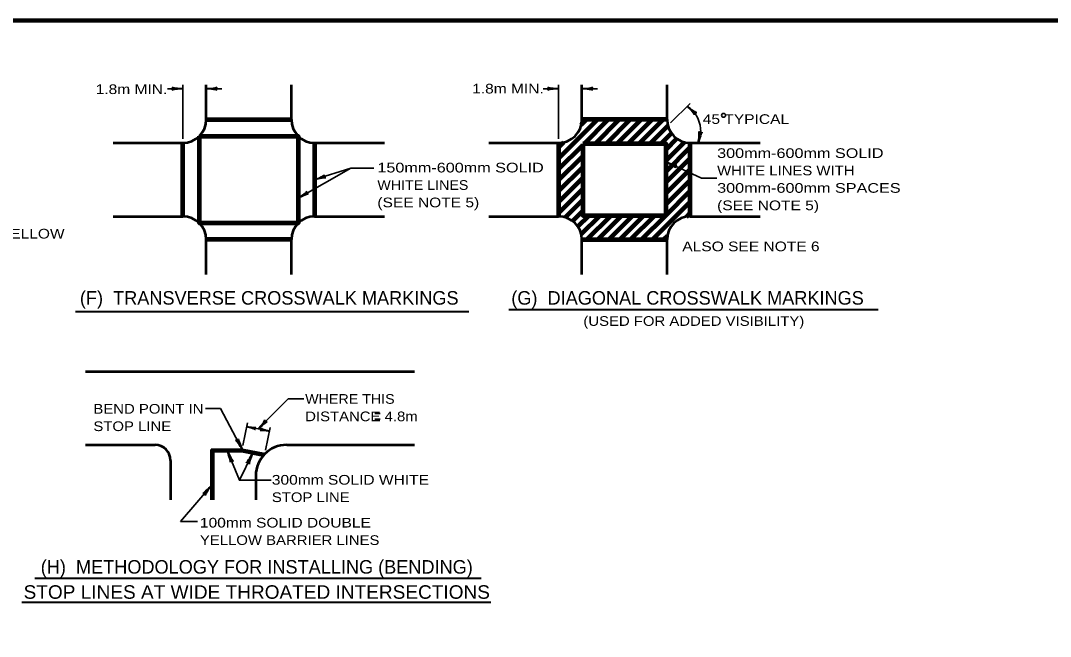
# Model space of a CAD drawing. Extents: x -90 to 765, y -1136 to -592.
# Drawn here: x 218.6 to 537.7, y -789.1 to -598.1 of the extents above; entities that cross this region are included whole.
import ezdxf
from ezdxf.enums import TextEntityAlignment as Align

# ---------------------------------------------------------------- set-up
doc = ezdxf.new("R2010")
doc.units = 0
doc.header["$LTSCALE"] = 1.2
doc.layers.add('1', color=7, linetype='Continuous', lineweight=90)

msp = doc.modelspace()

# ---------------------------------------------------------------- linework, layer by layer
at = {"layer": '1', "lineweight": 35}
for p, q in [((268.927, -634.812), (268.927, -618.013)), ((385.327, -634.812), (385.327, -618.013)), ((264.127, -619.212), (268.927, -619.212)), ((276.127, -619.212), (280.927, -619.212)), ((380.527, -619.212), (385.327, -619.212)), ((392.527, -619.212), (397.327, -619.212)), ((420.026, -629.849), (426.071, -623.803)), ((320.997, -643.903), (304.636, -653.164)), ((320.997, -643.903), (309.727, -647.413)), ((320.997, -643.903), (328.091, -643.903)), ((418.636, -641.864), (429.576, -646.983)), ((429.576, -646.983), (434.376, -646.983)), ((292.204, -724.718), (301.545, -715.368)), ((301.545, -715.368), (306.345, -715.368)), ((275.891, -718.43), (280.527, -718.43)), ((287.283, -731.075), (280.527, -718.43)), ((288.935, -722.839), (287.519, -729.898)), ((288.699, -724.015), (295.71, -725.421)), ((295.946, -724.245), (294.531, -731.304)), ((277.683, -742.387), (268.121, -753.418)), ((286.43, -740.631), (296.226, -740.631)), ((268.121, -753.418), (273.42, -753.418))]:
    msp.add_line(p, q, dxfattribs=at)
at = {"layer": '1', "lineweight": 53}
for p, q in [((276.127, -628.812), (276.127, -618.013)), ((302.527, -628.812), (302.527, -618.013)), ((392.527, -628.812), (392.527, -618.013)), ((418.927, -628.812), (418.927, -618.013)), ((247.327, -636.013), (268.927, -636.013)), ((309.727, -636.013), (331.327, -636.013)), ((363.727, -636.013), (385.327, -636.013)), ((426.127, -636.013), (447.727, -636.013)), ((247.327, -658.812), (268.927, -658.812)), ((309.727, -658.812), (331.327, -658.812)), ((363.727, -658.812), (385.327, -658.812)), ((426.127, -658.812), (447.727, -658.812)), ((276.127, -676.812), (276.127, -666.013)), ((302.527, -676.812), (302.527, -666.013)), ((392.527, -676.812), (392.527, -666.013)), ((418.927, -676.812), (418.927, -666.013)), ((238.683, -706.869), (340.683, -706.869)), ((238.683, -729.669), (260.283, -729.669)), ((301.083, -729.669), (340.683, -729.669)), ((277.683, -731.075), (277.683, -746.701)), ((277.683, -731.075), (287.283, -731.075)), ((278.283, -731.675), (278.283, -746.701)), ((278.283, -731.675), (287.224, -731.675)), ((287.224, -731.675), (293.816, -732.996)), ((287.283, -731.075), (294.295, -732.481)), ((265.083, -734.469), (265.083, -746.701)), ((291.483, -739.269), (291.483, -746.701))]:
    msp.add_line(p, q, dxfattribs=at)
at = {"layer": '1'}
for p, q in [((276.127, -628.812), (302.527, -628.812)), ((385.327, -640.816), (397.331, -628.812)), ((392.32, -630.43), (393.937, -628.812)), ((418.927, -628.812), (392.527, -628.812)), ((393.234, -636.304), (400.725, -628.812)), ((396.628, -636.304), (404.119, -628.812)), ((400.022, -636.304), (407.513, -628.812)), ((403.416, -636.304), (410.907, -628.812)), ((406.81, -636.304), (414.301, -628.812)), ((410.204, -636.304), (417.696, -628.812)), ((413.598, -636.304), (419.186, -630.717)), ((416.993, -636.304), (420.292, -633.004)), ((418.636, -638.055), (422, -634.69)), ((268.927, -658.812), (268.927, -636.013)), ((309.727, -636.013), (309.727, -658.812)), ((385.327, -637.422), (386.937, -635.813)), ((385.327, -636.013), (385.327, -658.812)), ((385.327, -644.21), (392.818, -636.719)), ((418.636, -641.449), (424.326, -635.759)), ((418.636, -644.843), (426.127, -637.351)), ((426.127, -658.812), (426.127, -636.013)), ((385.327, -647.605), (392.818, -640.113)), ((418.636, -648.237), (426.127, -640.746)), ((385.327, -650.999), (392.818, -643.507)), ((418.636, -651.631), (426.127, -644.14)), ((385.327, -654.393), (392.818, -646.902)), ((418.636, -655.025), (426.127, -647.534)), ((385.327, -657.787), (392.818, -650.296)), ((418.636, -658.419), (426.127, -650.928)), ((387.379, -659.129), (392.818, -653.69)), ((389.645, -660.258), (392.818, -657.084)), ((414.437, -666.013), (426.127, -654.322)), ((391.301, -661.995), (394.775, -658.521)), ((392.321, -664.369), (398.169, -658.521)), ((394.072, -666.013), (401.563, -658.521)), ((397.466, -666.013), (404.957, -658.521)), ((400.86, -666.013), (408.351, -658.521)), ((404.254, -666.013), (411.745, -658.521)), ((407.648, -666.013), (415.14, -658.521)), ((411.043, -666.013), (418.534, -658.521)), ((424.902, -658.942), (426.127, -657.716)), ((302.527, -666.013), (276.127, -666.013)), ((392.527, -666.013), (418.927, -666.013)), ((417.831, -666.013), (419.03, -664.813))]:
    msp.add_line(p, q, dxfattribs=at)
at = {"layer": '1', "lineweight": 40}
for p, q in [((235.632, -688.29), (357.466, -688.29)), ((369.929, -687.659), (484.337, -687.659)), ((223.054, -770.981), (361.353, -770.981)), ((219.033, -778.412), (364.368, -778.412))]:
    msp.add_line(p, q, dxfattribs=at)
at = {"layer": '1', "lineweight": 158}
msp.add_lwpolyline([(758.78, -598.088), (-32.92, -598.188), (-32.82, -1124.188)], dxfattribs=at)
at = {"layer": '1'}
for points in [[(274.018, -633.904), (304.636, -633.904), (304.636, -660.921), (274.018, -660.921)], [(392.818, -636.304), (392.818, -658.521), (418.636, -658.521), (418.636, -636.304)]]:
    msp.add_lwpolyline(points, close=True, dxfattribs=at)
at = {"layer": '1', "lineweight": 35}
msp.add_lwpolyline([(282.754, -731.675), (286.43, -740.631), (290.52, -732.336)], dxfattribs=at)
msp.add_circle((436.426, -627.48), 0.614, dxfattribs=at)
msp.add_arc((420.073, -632.376), 9.283, 352.39462, 42.67554, dxfattribs=at)
at = {"layer": '1', "lineweight": 53}
for centre, radius, start, end in [((268.927, -628.812), 7.2, 270, 0), ((309.727, -628.812), 7.2, 180, 270), ((385.327, -628.812), 7.2, 270, 0), ((426.127, -628.812), 7.2, 180, 270), ((268.927, -666.013), 7.2, 0, 90), ((309.727, -666.013), 7.2, 90, 180), ((385.327, -666.013), 7.2, 0, 90), ((426.127, -666.013), 7.2, 90, 180), ((260.283, -734.469), 4.8, 0, 90), ((301.083, -739.269), 9.6, 90, 180)]:
    msp.add_arc(centre, radius, start, end, dxfattribs=at)
at = {"layer": '1', "lineweight": 40}
for centre, major_axis, ratio, start_param, end_param in [((267.582, -618.959), (2.108, -0.211), 0.07063, 3.1407148, 5.41811), ((267.582, -618.959), (2.108, -0.211), 0.07063, 3.1407148, 5.41811), ((277.436, -618.881), (-2.143, -0.187), 0.122415, 0.8963533, 3.1415927), ((383.982, -618.959), (2.108, -0.211), 0.07063, 3.1407148, 5.41811), ((383.982, -618.959), (2.108, -0.211), 0.07063, 3.1407148, 5.41811), ((393.836, -618.881), (-2.143, -0.187), 0.122415, 0.8963533, 3.1415927), ((267.618, -619.544), (2.143, 0.187), 0.122415, 0.8963533, 3.1415927), ((267.618, -619.544), (2.143, 0.187), 0.122415, 0.8963533, 3.1415927), ((277.472, -619.466), (-2.108, 0.211), 0.07063, 3.1407148, 5.41811), ((384.018, -619.544), (2.143, 0.187), 0.122415, 0.8963533, 3.1415927), ((384.018, -619.544), (2.143, 0.187), 0.122415, 0.8963533, 3.1415927), ((393.872, -619.466), (-2.108, 0.211), 0.07063, 3.1407148, 5.41811), ((426.047, -625.76), (-1.415, 1.576), 0.07063, 3.1407148, 5.41811), ((426.415, -625.304), (-1.709, 1.306), 0.122415, 0.8963533, 3.1415927), ((428.548, -634.655), (-0.222, -2.14), 0.122415, 0.8963533, 3.1415927), ((429.13, -634.732), (-0.606, -2.03), 0.07063, 3.1407148, 5.41811), ((419.746, -642.664), (-1.82, 1.084), 0.07063, 3.1407148, 5.41811), ((419.962, -642.119), (-2.02, 0.738), 0.122415, 0.8963533, 3.1415927), ((310.879, -646.707), (-1.99, -0.816), 0.122415, 0.8963533, 3.1415927), ((311.086, -647.255), (-2.075, -0.425), 0.07063, 3.1407148, 5.41811), ((305.612, -652.23), (-1.773, -1.219), 0.122415, 0.8963533, 3.1415927), ((305.931, -652.722), (-1.938, -0.855), 0.07063, 3.1407148, 5.41811), ((289.733, -724.44), (-1.64, 0.503), 0.07063, 3.1407148, 5.41811), ((289.798, -723.97), (-1.732, 0.192), 0.122415, 0.8963533, 3.1415927), ((292.895, -723.557), (-1.382, -1.648), 0.122415, 0.8963533, 3.1415927), ((292.895, -723.557), (-1.382, -1.648), 0.122415, 0.8963533, 3.1415927), ((293.334, -723.946), (-1.639, -1.342), 0.07063, 3.1407148, 5.41811), ((293.334, -723.946), (-1.639, -1.342), 0.07063, 3.1407148, 5.41811), ((294.611, -725.466), (1.732, -0.192), 0.122415, 0.8963533, 3.1415927), ((294.676, -724.996), (1.64, -0.503), 0.07063, 3.1407148, 5.41811), ((286.374, -730.076), (1.175, -1.802), 0.122415, 0.8963533, 3.1415927), ((286.874, -729.769), (0.807, -1.958), 0.07063, 3.1407148, 5.41811), ((283.029, -733.015), (-0.605, 2.03), 0.07063, 3.1407148, 5.41811), ((283.029, -733.015), (-0.605, 2.03), 0.07063, 3.1407148, 5.41811), ((283.558, -732.76), (-0.987, 1.911), 0.122415, 0.8963533, 3.1415927), ((283.558, -732.76), (-0.987, 1.911), 0.122415, 0.8963533, 3.1415927), ((289.698, -733.429), (1.121, 1.797), 0.07063, 3.1407148, 5.41811), ((290.238, -733.657), (0.779, 2.005), 0.122415, 0.8963533, 3.1415927), ((276.611, -743.237), (1.54, 1.455), 0.07063, 3.1407148, 5.41811), ((277.076, -743.594), (1.262, 1.742), 0.122415, 0.8963533, 3.1415927)]:
    msp.add_ellipse(centre, major_axis=major_axis, ratio=ratio, start_param=start_param, end_param=end_param, dxfattribs=at)

# ---------------------------------------------------------------- texts
at = {"layer": '1'}
for s, height, width, p in [('1.8m MIN.', 3, 1.2, (252.98, -620.875)), ('1.8m MIN.', 3, 1.2, (369.634, -620.697)), ('45 TYPICAL', 3, 1.2, (443.37, -630.14)), ('ALSO SEE NOTE 6', 3, 1.2, (444.922, -669.622)), ('(USED FOR ADDED VISIBILITY)', 3, 1.15, (427.215, -692.764)), ('=', 4.8, 0.55, (329.192, -723.127)), ('STOP LINES AT WIDE THROATED INTERSECTIONS', 4.2, 1.05, (291.8, -777.406))]:
    msp.add_text(s, height=height, dxfattribs=dict(at, width=width)).set_placement(p, align=Align.CENTER)
for s, width, p in [('300mm-600mm SOLID', 1.25, (434.444, -640.692)), ('150mm-600mm SOLID', 1.25, (329.166, -645.185)), ('WHITE LINES WITH', 1.15, (434.444, -646.092)), ('WHITE LINES', 1.1, (329.166, -650.585)), ('300mm-600mm SPACES', 1.25, (434.444, -651.492)), ('(SEE NOTE 5)', 1.2, (329.166, -655.985)), ('(SEE NOTE 5)', 1.2, (434.444, -656.892)), ('100mm SOLID DOUBLE YELLOW', 1.2, (157.894, -665.678)), ('WHERE THIS', 1.1, (306.807, -716.933)), ('BEND POINT IN', 1.15, (241.181, -719.995)), ('DISTANCE 4.8m', 1.15, (306.807, -722.333)), ('STOP LINE', 1.15, (241.181, -725.395)), ('300mm SOLID WHITE', 1.2, (296.475, -742.005)), ('STOP LINE', 1.15, (296.475, -747.404)), ('100mm SOLID DOUBLE', 1.2, (274.185, -755.306)), ('YELLOW BARRIER LINES', 1.15, (274.185, -760.706))]:
    msp.add_text(s, height=3, dxfattribs=dict(at, width=width)).set_placement(p)
for s, p in [('(F)  TRANSVERSE CROSSWALK MARKINGS', (236.999, -686.187)), ('(G)  DIAGONAL CROSSWALK MARKINGS', (370.665, -686.187))]:
    msp.add_text(s, height=4.2, dxfattribs=at).set_placement(p)
msp.add_text('(H)  METHODOLOGY FOR INSTALLING (BENDING)', height=4.2, dxfattribs=at).set_placement((291.8, -769.606), align=Align.CENTER)

doc.saveas('drawing.dxf')
